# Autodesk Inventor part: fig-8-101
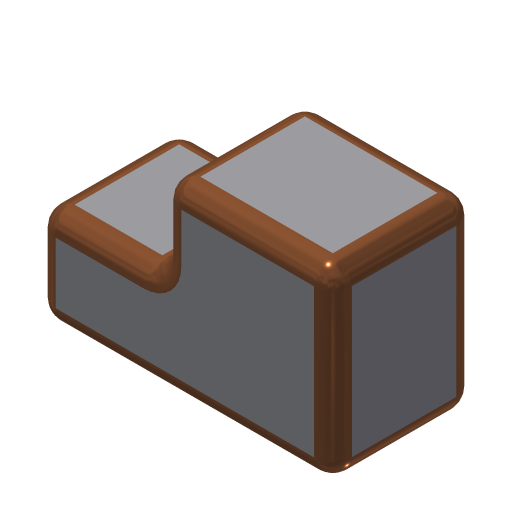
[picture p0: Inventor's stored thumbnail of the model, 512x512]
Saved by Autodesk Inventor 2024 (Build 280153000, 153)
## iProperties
Shininess: 64.0
Length Units: 11269
Angle Units: 11279
Time Units: 11290
Mass Units: 11283
Length Display Precision: 3
Angle Display Precision: 2
Compacted: True
Part Number: fig-8-101
Document SubType Name: Modeling
Created: 2002-12
Designer: deepak
Density: 1 g/cm^3
Material: Generic
Appearance: Default
Density: 0.0
Volumn: 0.0
Area: 0.0
PropertySet Name: Model Information
Control State: 0
Master: False
Checked Out: False
Author: deepak
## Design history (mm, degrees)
sketch "Sketch1"
  geometry: L1 (-26.972, 23.346)-(8.906, 23.346); L2 (8.906, 23.346)-(8.906, 5.025); L3 (8.906, -15.84)-(-26.972, -15.84); L4 (-26.972, -15.84)-(-26.972, 23.346); L5 (8.906, -15.84)-(35.369, -15.84); L6 (35.369, -15.84)-(35.369, 5.025); L7 (35.369, 5.025)-(8.906, 5.025)
  constraints: 14 end point, 3 parallel, 2 horizontal, 2 perpendicular
extrude "Extrusion1" new body sketch "Sketch1" stored distance "d0" = 30; taper "d1" = 0 deg
fillet "Fillet1" dims "d2" = 4, "d3" = 4
body "Solid1"
